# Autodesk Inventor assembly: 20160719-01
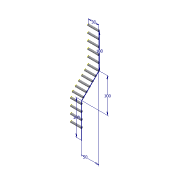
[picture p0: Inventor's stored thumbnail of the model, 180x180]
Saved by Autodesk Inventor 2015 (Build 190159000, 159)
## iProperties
Created: 2016-07
Part Number: 20160719-01
Document SubType Name: Assembly
Designer: navara
Mass: 8.83573 g
Surface Area: 76.5763 cm^2
Volume: 8.83573 cm^3
Density: 1 g/cm^3
Mass: 8,8 g
Author: navara
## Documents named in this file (3)
- D:\Dokumenty\CAD_DATA\Inventor_2015\Projekty\SOUCASTKY_2015\20160719\20160719-01.iam
- D:\Dokumenty\CAD_DATA\Inventor_2015\Projekty\SOUCASTKY_2015\20160719\20160719-01.ipt
- D:\Dokumenty\CAD_DATA\Inventor_2015\Projekty\SOUCASTKY_2015\20160719\20160719-02.ipt
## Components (16 placed, 2 different names)
1. 20160719-01:1 — Proti sobě:2, Proti sobě:3
2. 20160719-02:1 — Proti sobě:2, Proti sobě:3
3. 20160719-02:2
4. 20160719-02:3
5. 20160719-02:4
6. 20160719-02:5
7. 20160719-02:6
8. 20160719-02:7
9. 20160719-02:8
10. 20160719-02:9
11. 20160719-02:10
12. 20160719-02:11
13. 20160719-02:12
14. 20160719-02:13
15. 20160719-02:14
16. 20160719-02:15
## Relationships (2: Mate 2)
- Proti sobě:2 [Mate]: 20160719-01:1 ↔ 20160719-02:1
- Proti sobě:3 [Mate]: 20160719-01:1 ↔ 20160719-02:1
